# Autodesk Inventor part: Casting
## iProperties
Shininess: 77.0
Length Units: 11269
Angle Units: 11279
Time Units: 11290
Mass Units: 11283
Length Display Precision: 3
Angle Display Precision: 2
Created: 2002-02
Part Number: Casting
Document SubType Name: Modeling
Designer: ***
Description: Sample Casting
Density: 0.0
Volumn: 0.0
Area: 0.0
PropertySet Name: Model Information
Control State: 0
Master: False
Checked Out: False
Author: ***
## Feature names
1. Extrusion1
2. Extrusion2
3. Extrusion3
4. Extrusion4
5. Extrusion5
6. Mirror1
7. Extrusion6
